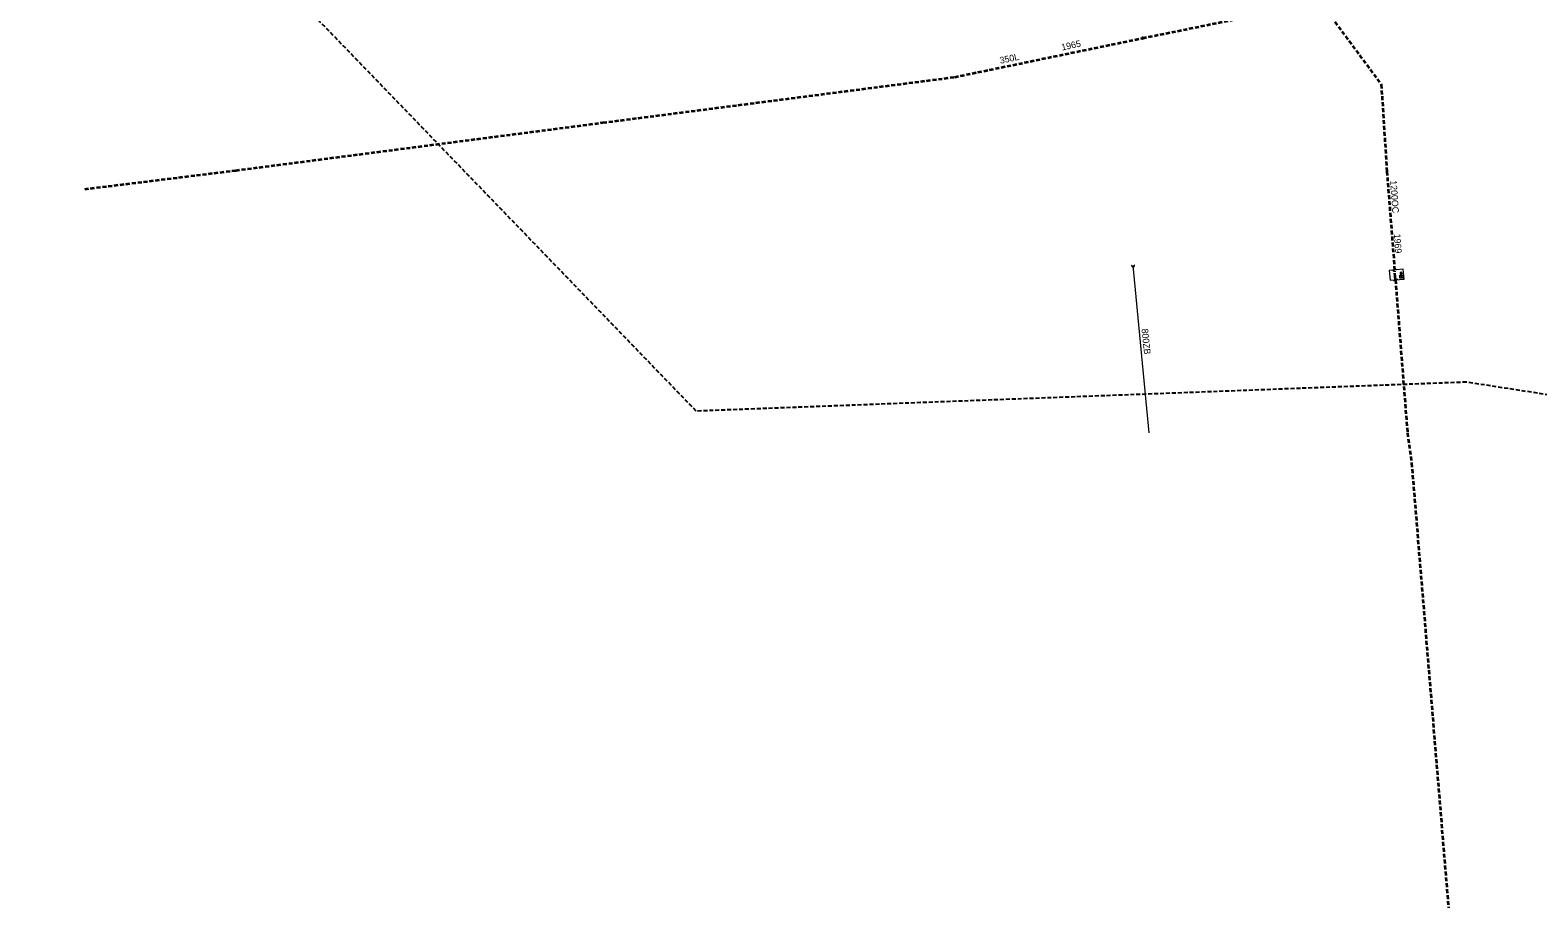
# Model space of a CAD drawing. Extents: x -735085 to -733500, y -1044153 to -1043402.
# Drawn here: x -734957.7 to -734591.8, y -1043928.8 to -1043715.9 of the extents above; entities that cross this region are included whole.
import ezdxf

# ---------------------------------------------------------------- set-up
doc = ezdxf.new("R2010")
doc.units = 0
doc.header["$LTSCALE"] = 0.32
doc.linetypes.add('DOT_DASHED', pattern=[7.7, 5, -1.2, 0.3, -1.2])
doc.linetypes.add('MEDIUM_DASHED', pattern=[4.5, 3, -1.5])
doc.layers.add('15', color=7, linetype='Continuous')
doc.layers.add('63', color=7, linetype='MEDIUM_DASHED', lineweight=25)
doc.layers.add('8', color=7, linetype='Continuous', lineweight=13)

msp = doc.modelspace()

# ---------------------------------------------------------------- linework, layer by layer
at = {"layer": '63'}
msp.add_lwpolyline([(-734446.739, -1043826.44), (-734609.112, -1043801.262), (-734796.014, -1043808.282), (-734796.016, -1043808.281), (-734796.018, -1043808.281), (-734796.02, -1043808.28), (-734796.022, -1043808.279), (-734957.658, -1043641.023)], dxfattribs=at)
at = {"layer": '8'}
for p, q in [((-734690.294, -1043772.949), (-734690.354, -1043772.954)), ((-734686.059, -1043813.52), (-734689.999, -1043772.929)), ((-734689.647, -1043772.886), (-734689.707, -1043772.892))]:
    msp.add_line(p, q, dxfattribs=at)
at = {"layer": '8', "linetype": 'DOT_DASHED', "lineweight": 35}
msp.add_line((-734626.331, -1043776.443), (-734626.521, -1043774.035), dxfattribs=at)
at = {"layer": '8', "linetype": 'MEDIUM_DASHED', "lineweight": 35}
for points in [[(-734668.849, -1043580.305), (-734675.546, -1043596.328), (-734683.508, -1043610.677), (-734694.054, -1043642.408), (-734687.381, -1043651.433), (-734629.763, -1043729.041), (-734628.401, -1043750.135), (-734626.521, -1043774.035)], [(-734687.657, -1043717.791), (-734560.96, -1043692.026), (-734536.445, -1043703.655)], [(-734944.42, -1043754.43), (-734942.98, -1043754.25), (-734907.765, -1043749.891), (-734818.64, -1043738.299), (-734733.272, -1043727.24), (-734687.657, -1043717.791)], [(-734626.331, -1043776.443), (-734623.409, -1043813.588), (-734622.397, -1043820.945), (-734613.463, -1043928.794)]]:
    msp.add_lwpolyline(points, dxfattribs=at)
at = {"layer": '8'}
for points in [[(-734687.426, -1043717.78), (-734687.432, -1043717.728), (-734687.45, -1043717.678), (-734687.478, -1043717.634), (-734687.516, -1043717.597), (-734687.561, -1043717.57), (-734687.611, -1043717.554), (-734687.663, -1043717.549), (-734687.715, -1043717.556), (-734687.764, -1043717.575), (-734687.808, -1043717.605), (-734687.843, -1043717.644), (-734687.869, -1043717.689), (-734687.884, -1043717.74), (-734687.887, -1043717.792), (-734687.879, -1043717.844), (-734687.858, -1043717.892), (-734687.828, -1043717.935), (-734687.788, -1043717.97), (-734687.742, -1043717.994), (-734687.691, -1043718.008), (-734687.639, -1043718.01), (-734687.587, -1043718), (-734687.539, -1043717.978), (-734687.497, -1043717.946), (-734687.464, -1043717.906), (-734687.44, -1043717.859), (-734687.428, -1043717.808)], [(-734627.84, -1043774.145), (-734627.638, -1043776.552), (-734624.215, -1043776.267), (-734624.416, -1043773.86)], [(-734625.266, -1043775.263), (-734624.476, -1043775.263), (-734624.476, -1043776.063), (-734625.266, -1043776.063)], [(-734624.728, -1043774.839), (-734624.735, -1043774.787), (-734624.752, -1043774.737), (-734624.781, -1043774.693), (-734624.819, -1043774.656), (-734624.864, -1043774.629), (-734624.914, -1043774.613), (-734624.966, -1043774.608), (-734625.017, -1043774.615), (-734625.066, -1043774.634), (-734625.11, -1043774.664), (-734625.146, -1043774.703), (-734625.172, -1043774.748), (-734625.186, -1043774.799), (-734625.19, -1043774.851), (-734625.181, -1043774.903), (-734625.161, -1043774.951), (-734625.13, -1043774.994), (-734625.091, -1043775.029), (-734625.044, -1043775.053), (-734624.994, -1043775.067), (-734624.941, -1043775.069), (-734624.89, -1043775.059), (-734624.842, -1043775.037), (-734624.799, -1043775.005), (-734624.767, -1043774.965), (-734624.743, -1043774.918), (-734624.73, -1043774.867)]]:
    msp.add_lwpolyline(points, close=True, dxfattribs=at)
for points in [[(-734690.354, -1043772.954), (-734690.34, -1043773.025), (-734690.316, -1043773.093), (-734690.284, -1043773.156), (-734690.244, -1043773.212), (-734690.198, -1043773.259), (-734690.147, -1043773.296), (-734690.091, -1043773.323), (-734690.033, -1043773.338), (-734689.974, -1043773.342), (-734689.917, -1043773.333), (-734689.862, -1043773.313), (-734689.81, -1043773.281), (-734689.763, -1043773.24), (-734689.723, -1043773.189), (-734689.691, -1043773.129), (-734689.667, -1043773.065), (-734689.651, -1043772.995), (-734689.646, -1043772.923), (-734689.647, -1043772.886)], [(-734690.294, -1043772.949), (-734690.281, -1043773.014), (-734690.259, -1043773.075), (-734690.229, -1043773.13), (-734690.191, -1043773.179), (-734690.147, -1043773.219), (-734690.098, -1043773.248), (-734690.046, -1043773.267), (-734689.993, -1043773.274), (-734689.939, -1043773.269), (-734689.889, -1043773.252), (-734689.841, -1043773.223), (-734689.799, -1043773.185), (-734689.763, -1043773.137), (-734689.735, -1043773.082), (-734689.717, -1043773.022), (-734689.707, -1043772.957), (-734689.707, -1043772.892)], [(-734626.463, -1043773.793), (-734626.035, -1043773.903), (-734626.967, -1043774.156), (-734626.583, -1043774.289)], [(-734626.274, -1043776.201), (-734625.846, -1043776.311), (-734626.778, -1043776.564), (-734626.394, -1043776.697)], [(-734625.039, -1043775.846), (-734625.029, -1043775.889), (-734625.007, -1043775.928), (-734624.976, -1043775.959), (-734624.938, -1043775.98), (-734624.895, -1043775.991), (-734624.851, -1043775.989), (-734624.809, -1043775.976), (-734624.772, -1043775.952), (-734624.743, -1043775.919), (-734624.724, -1043775.879), (-734624.716, -1043775.836), (-734624.72, -1043775.792), (-734624.736, -1043775.751), (-734624.762, -1043775.716), (-734624.797, -1043775.689), (-734624.838, -1043775.672), (-734624.864, -1043775.667)], [(-734624.717, -1043775.509), (-734624.722, -1043775.466), (-734624.739, -1043775.425), (-734624.766, -1043775.391), (-734624.802, -1043775.365), (-734624.843, -1043775.35), (-734624.886, -1043775.347), (-734624.929, -1043775.355), (-734624.968, -1043775.375), (-734625.001, -1043775.404), (-734625.024, -1043775.442), (-734625.036, -1043775.484), (-734625.037, -1043775.527), (-734625.025, -1043775.57), (-734625.003, -1043775.607), (-734624.971, -1043775.638), (-734624.933, -1043775.658), (-734624.89, -1043775.667), (-734624.864, -1043775.667)]]:
    msp.add_lwpolyline(points, dxfattribs=at)

# ---------------------------------------------------------------- texts
at = {"layer": '15'}
for s, rotation, p in [('1965', 12, (-734707.214, -1043720.819)), ('350L', 12, (-734722.186, -1043724.03)), ('1200OC', 274, (-734627.617, -1043752.352)), ('1969', 274, (-734626.711, -1043765.305)), ('800ZB ', 276, (-734687.952, -1043788.357))]:
    msp.add_text(s, height=1.6, rotation=rotation, dxfattribs=at).set_placement(p)

doc.saveas('drawing.dxf')
